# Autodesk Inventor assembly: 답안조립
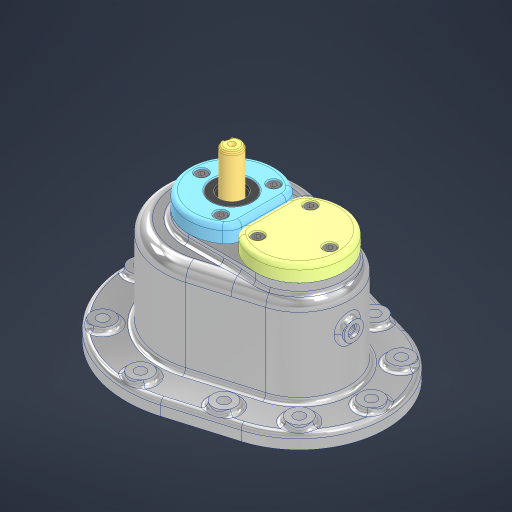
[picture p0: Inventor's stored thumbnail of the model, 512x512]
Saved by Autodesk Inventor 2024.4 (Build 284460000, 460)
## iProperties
Created: 2026-03
Part Number: 답안조립
Document SubType Name: Assembly
Designer: user
Author: user
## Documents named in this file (13)
- C:\Users\user\Desktop\760303V1008\답안조립.iam
- C:\Users\user\Desktop\760303V1008\본체.ipt
- C:\Users\user\Desktop\760303V1008\깊은 홈 볼 베어링 6001\깊은 홈 볼 베어링 6001\깊은 홈 볼 베어링 6001.ipt
- C:\Users\user\Desktop\760303V1008\기어 축\기어 축\기어 축.ipt
- C:\Users\user\Desktop\760303V1008\C형 멈춤링 구멍용 28\C형 멈춤링 구멍용 28\C형 멈춤링 구멍용 28.ipt
- C:\Users\user\Desktop\760303V1008\축\축\축.ipt
- C:\Users\user\Desktop\760303V1008\스퍼 기어\스퍼 기어\스퍼 기어.ipt
- C:\Users\user\Desktop\760303V1008\칼라\칼라\칼라.ipt
- C:\Users\user\Desktop\760303V1008\평행 키 4x4x12\평행 키 4x4x12\평행 키 4x4x12.ipt
- C:\Users\user\Desktop\760303V1008\오일 실 12 25 7\오일 실 12 25 7\오일 실 12 25 7.ipt
- C:\Users\user\Desktop\760303V1008\상부 커버\상부 커버\상부 커버.ipt
- C:\Users\user\Desktop\760303V1008\하부 커버\하부 커버\하부 커버.ipt
- C:\Users\user\Desktop\760303V1008\6각 구멍붙이 볼트 M4x10\6각 구멍붙이 볼트 M4x10\6각 구멍붙이 볼트 M4x10.ipt
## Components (8 placed, 3 different names)
1. C형 멈춤링 구멍용 28:1
2. 하부 커버:1
3. 6각 구멍붙이 볼트 M4x10:1
4. 6각 구멍붙이 볼트 M4x10:2
5. 6각 구멍붙이 볼트 M4x10:3
6. 6각 구멍붙이 볼트 M4x10:4
7. 6각 구멍붙이 볼트 M4x10:5
8. 6각 구멍붙이 볼트 M4x10:6
